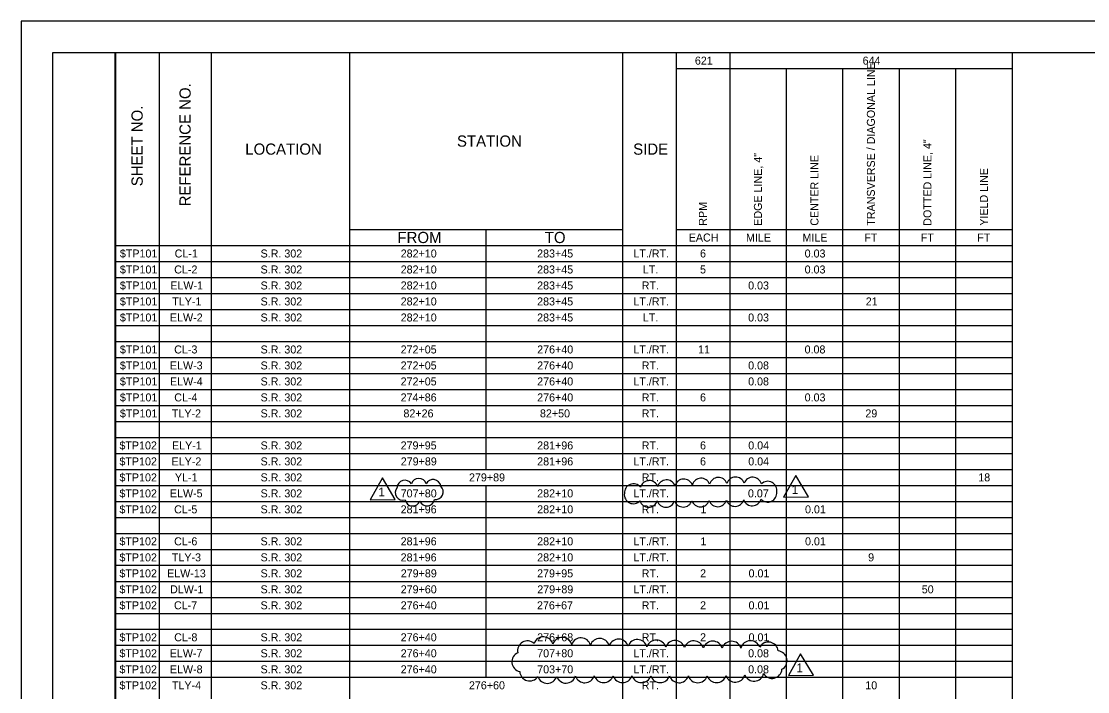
# Model space of a CAD drawing. Extents: x 0 to 34, y 0 to 22.
# Drawn here: x 0 to 17, y 11.3 to 22 of the extents above; entities that cross this region are included whole.
import ezdxf

# ---------------------------------------------------------------- set-up
doc = ezdxf.new("R2010")
doc.units = 0
for name, color, linetype in [('SC_Scratch2', 7, 'Continuous'), ('SH_Border', 7, 'Continuous'), ('SH_Cut_Line', 7, 'Continuous'), ('SH_Data', 7, 'Continuous'), ('SH_Text', 7, 'Continuous')]:
    doc.layers.add(name, color=color, linetype=linetype)

msp = doc.modelspace()

# ---------------------------------------------------------------- linework, layer by layer
at = {"layer": 'SC_Scratch2'}
for points in [[(5.962, 14.373), (5.757, 14.716), (5.563, 14.368)], [(12.55, 14.413), (12.346, 14.755), (12.152, 14.407)], [(12.627, 11.567), (12.422, 11.909), (12.228, 11.561)]]:
    msp.add_lwpolyline(points, close=True, dxfattribs=at)
for centre, radius, start, end in [((6.113, 14.555), 0.124, 32.3184, 177.3184), ((6.336, 14.584), 0.124, 17.5, 162.5), ((6.564, 14.566), 0.124, 8.4917, 153.4917), ((9.758, 14.477), 0.144, 38.7518, 183.7518), ((10.01, 14.529), 0.144, 19.5813, 164.5813), ((10.286, 14.541), 0.144, 20.0695, 165.0695), ((10.562, 14.554), 0.144, 20.3092, 165.3092), ((10.837, 14.567), 0.144, 20.3857, 165.3857), ((11.112, 14.579), 0.144, 19.6335, 164.6335), ((11.386, 14.586), 0.144, 18.1718, 163.1718), ((11.659, 14.582), 0.144, 15.1046, 160.1046), ((11.901, 14.517), 0.144, 349.9389, 134.9389), ((6.085, 14.483), 0.124, 140.5725, 285.5725), ((6.603, 14.493), 0.123, 262.705, 47.705), ((9.757, 14.448), 0.144, 172.0953, 317.0953), ((11.899, 14.474), 0.145, 222.0236, 7.0236), ((6.239, 14.391), 0.124, 192.5799, 337.5799), ((6.466, 14.394), 0.124, 204.1379, 349.1379), ((10.001, 14.392), 0.144, 197.1764, 342.1764), ((10.276, 14.392), 0.144, 197.8033, 342.8033), ((10.552, 14.394), 0.144, 197.9714, 342.9714), ((10.827, 14.397), 0.144, 198.0611, 343.0611), ((11.103, 14.4), 0.144, 198.2873, 343.2873), ((11.378, 14.405), 0.144, 198.8892, 343.8892), ((11.652, 14.415), 0.145, 200.123, 345.123), ((8.068, 11.959), 0.157, 47.3954, 192.3954), ((8.323, 12.023), 0.157, 15.8432, 160.8432), ((8.623, 12.014), 0.157, 15.8432, 160.8432), ((8.922, 12.006), 0.157, 15.8432, 160.8432), ((9.222, 11.997), 0.157, 15.8432, 160.8432), ((9.522, 11.988), 0.157, 15.8432, 160.8432), ((9.822, 11.98), 0.157, 15.8994, 160.8994), ((10.122, 11.972), 0.157, 16.0369, 161.0369), ((10.422, 11.965), 0.157, 16.2188, 161.2188), ((10.722, 11.959), 0.157, 16.4757, 161.4757), ((11.023, 11.954), 0.157, 16.8801, 161.8801), ((11.323, 11.953), 0.157, 17.6722, 162.6722), ((11.625, 11.961), 0.157, 20.3498, 165.3498), ((11.91, 11.94), 0.157, 5.9617, 150.9617), ((7.977, 11.781), 0.157, 113.5219, 258.5219), ((12.05, 11.8), 0.157, 298.8755, 83.8755), ((8.103, 11.633), 0.157, 182.0686, 327.0686), ((9.585, 11.607), 0.157, 197.5241, 342.5241), ((9.885, 11.607), 0.157, 197.3438, 342.3438), ((11.084, 11.606), 0.157, 198.3726, 343.3726), ((11.383, 11.614), 0.157, 199.5171, 344.5171), ((11.68, 11.63), 0.157, 201.7062, 346.7062), ((11.969, 11.674), 0.157, 210.6115, 355.6115), ((8.385, 11.595), 0.157, 197.644, 342.644), ((8.683, 11.599), 0.157, 198.8809, 343.8809), ((8.984, 11.604), 0.157, 198.162, 343.162), ((9.284, 11.607), 0.157, 197.7754, 342.7754), ((10.185, 11.606), 0.157, 197.2063, 342.2063), ((10.485, 11.604), 0.157, 197.1755, 342.1755), ((10.784, 11.604), 0.157, 197.6389, 342.6389)]:
    msp.add_arc(centre, radius, start, end, dxfattribs=at)
at = {"layer": 'SH_Border'}
for points in [[(0.5, 21.5), (1.5, 21.5), (1.5, 0.5), (0.5, 0.5)], [(1.5, 21.5), (33.5, 21.5), (33.5, 0.5), (1.5, 0.5)]]:
    msp.add_lwpolyline(points, close=True, dxfattribs=at)
at = {"layer": 'SH_Cut_Line'}
msp.add_lwpolyline([(0, 0), (34, 0), (34, 22), (0, 22)], close=True, dxfattribs=at)
at = {"layer": 'SH_Data'}
for p, q in [((1.493, 21.5), (15.796, 21.5)), ((1.493, 21.5), (1.493, 1.569)), ((2.198, 21.5), (2.198, 2.095)), ((3.024, 21.5), (3.024, 2.095)), ((5.23, 21.5), (5.23, 2.095)), ((9.582, 21.5), (9.582, 2.095)), ((10.438, 21.5), (10.438, 1.569)), ((11.293, 21.5), (11.293, 1.569)), ((15.796, 21.5), (15.796, 1.569)), ((10.438, 21.245), (15.796, 21.245)), ((12.194, 21.245), (12.194, 1.569)), ((13.094, 21.245), (13.094, 1.569)), ((13.995, 21.245), (13.995, 1.569)), ((14.895, 21.245), (14.895, 1.569)), ((5.23, 18.678), (9.582, 18.678)), ((7.406, 18.678), (7.406, 14.851)), ((10.438, 18.678), (15.796, 18.678)), ((1.493, 18.423), (15.796, 18.423)), ((1.493, 18.168), (15.796, 18.168)), ((1.493, 17.913), (15.796, 17.913)), ((1.493, 17.658), (15.796, 17.658)), ((1.493, 17.403), (15.796, 17.403)), ((1.493, 17.148), (15.796, 17.148)), ((1.493, 16.893), (15.796, 16.893)), ((1.493, 16.637), (15.796, 16.637)), ((1.493, 16.382), (15.796, 16.382)), ((1.493, 16.127), (15.796, 16.127)), ((1.493, 15.872), (15.796, 15.872)), ((1.493, 15.617), (15.796, 15.617)), ((1.493, 15.362), (15.796, 15.362)), ((1.493, 15.107), (15.796, 15.107)), ((1.493, 14.851), (15.796, 14.851)), ((1.493, 14.596), (15.796, 14.596)), ((7.406, 14.596), (7.406, 11.535)), ((1.493, 14.341), (15.796, 14.341)), ((1.493, 14.086), (15.796, 14.086)), ((1.493, 13.831), (15.796, 13.831)), ((1.493, 13.576), (15.796, 13.576)), ((1.493, 13.321), (15.796, 13.321)), ((1.493, 13.065), (15.796, 13.065)), ((1.493, 12.81), (15.796, 12.81)), ((1.493, 12.555), (15.796, 12.555)), ((1.493, 12.3), (15.796, 12.3)), ((1.493, 12.045), (15.796, 12.045)), ((1.493, 11.79), (15.796, 11.79)), ((1.493, 11.535), (15.796, 11.535))]:
    msp.add_line(p, q, dxfattribs=at)

# ---------------------------------------------------------------- texts
at = {"layer": 'SC_Scratch2'}
for p in [(5.692, 14.421), (12.281, 14.461), (12.357, 11.615)]:
    msp.add_text('1', height=0.14, dxfattribs=at).set_placement(p)
at = {"layer": 'SH_Text'}
for s, height, p in [('621', 0.1276, (10.738, 21.309)), ('644', 0.1276, (13.412, 21.309)), ('STATION', 0.1786, (6.945, 20)), ('LOCATION', 0.1786, (3.57, 19.872)), ('SIDE', 0.1786, (9.754, 19.872)), ('FROM', 0.1786, (5.996, 18.462)), ('TO', 0.1786, (8.345, 18.462)), ('EACH', 0.1276, (10.64, 18.487)), ('MILE', 0.1276, (11.553, 18.487)), ('MILE', 0.1276, (12.453, 18.487)), ('FT', 0.1276, (13.439, 18.487)), ('FT', 0.1276, (14.339, 18.487)), ('FT', 0.1276, (15.24, 18.487)), ('$TP101', 0.1276, (1.571, 18.232)), ('CL-1', 0.1276, (2.444, 18.232)), ('S.R. 302', 0.1276, (3.814, 18.232)), ('282+10', 0.1276, (6.048, 18.232)), ('283+45', 0.1276, (8.223, 18.232)), ('LT./RT.', 0.1276, (9.758, 18.232)), ('6', 0.128, (10.82, 18.232)), ('0.03', 0.1276, (12.488, 18.232)), ('$TP101', 0.1276, (1.571, 17.977)), ('CL-2', 0.1276, (2.437, 17.977)), ('S.R. 302', 0.1276, (3.814, 17.977)), ('282+10', 0.1276, (6.048, 17.977)), ('283+45', 0.1276, (8.223, 17.977)), ('LT.', 0.1276, (9.908, 17.977)), ('5', 0.128, (10.82, 17.977)), ('0.03', 0.1276, (12.488, 17.977)), ('$TP101', 0.1276, (1.571, 17.722)), ('S.R. 302', 0.1276, (3.814, 17.722)), ('282+10', 0.1276, (6.048, 17.722)), ('283+45', 0.1276, (8.223, 17.722)), ('0.03', 0.1276, (11.587, 17.722)), ('ELW-1', 0.1276, (2.375, 17.722)), ('RT.', 0.1276, (9.89, 17.722)), ('$TP101', 0.1276, (1.571, 17.467)), ('TLY-1', 0.1276, (2.406, 17.467)), ('S.R. 302', 0.1276, (3.814, 17.467)), ('282+10', 0.1276, (6.048, 17.467)), ('283+45', 0.1276, (8.223, 17.467)), ('LT./RT.', 0.1276, (9.758, 17.467)), ('21', 0.1276, (13.462, 17.467)), ('$TP101', 0.1276, (1.571, 17.211)), ('ELW-2', 0.1276, (2.369, 17.211)), ('S.R. 302', 0.1276, (3.814, 17.211)), ('282+10', 0.1276, (6.048, 17.211)), ('283+45', 0.1276, (8.223, 17.211)), ('0.03', 0.1276, (11.587, 17.211)), ('LT.', 0.1276, (9.908, 17.211)), ('$TP101', 0.1276, (1.571, 16.701)), ('CL-3', 0.1276, (2.437, 16.701)), ('S.R. 302', 0.1276, (3.814, 16.701)), ('272+05', 0.1276, (6.047, 16.701)), ('276+40', 0.1276, (8.224, 16.701)), ('LT./RT.', 0.1276, (9.758, 16.701)), ('0.08', 0.1276, (12.487, 16.701)), ('11', 0.1276, (10.789, 16.701)), ('$TP101', 0.1276, (1.571, 16.446)), ('ELW-3', 0.1276, (2.369, 16.446)), ('S.R. 302', 0.1276, (3.814, 16.446)), ('272+05', 0.1276, (6.047, 16.446)), ('276+40', 0.1276, (8.224, 16.446)), ('RT.', 0.1276, (9.89, 16.446)), ('0.08', 0.1276, (11.587, 16.446)), ('$TP101', 0.1276, (1.571, 16.191)), ('S.R. 302', 0.1276, (3.814, 16.191)), ('272+05', 0.1276, (6.047, 16.191)), ('276+40', 0.1276, (8.224, 16.191)), ('LT./RT.', 0.1276, (9.758, 16.191)), ('0.08', 0.1276, (11.587, 16.191)), ('ELW-4', 0.1276, (2.37, 16.191)), ('$TP101', 0.1276, (1.571, 15.936)), ('CL-4', 0.1276, (2.438, 15.936)), ('S.R. 302', 0.1276, (3.814, 15.936)), ('274+86', 0.1276, (6.047, 15.936)), ('276+40', 0.1276, (8.224, 15.936)), ('RT.', 0.1276, (9.89, 15.936)), ('6', 0.128, (10.82, 15.936)), ('0.03', 0.1276, (12.488, 15.936)), ('$TP101', 0.1276, (1.571, 15.681)), ('TLY-2', 0.1276, (2.4, 15.681)), ('S.R. 302', 0.1276, (3.814, 15.681)), ('82+26', 0.1276, (6.092, 15.681)), ('82+50', 0.1276, (8.268, 15.681)), ('29', 0.1276, (13.456, 15.681)), ('RT.', 0.1276, (9.89, 15.681)), ('$TP102', 0.1276, (1.564, 15.17)), ('ELY-1', 0.1276, (2.402, 15.17)), ('S.R. 302', 0.1276, (3.814, 15.17)), ('279+95', 0.1276, (6.047, 15.17)), ('281+96', 0.1276, (8.224, 15.17)), ('RT.', 0.1276, (9.89, 15.17)), ('6', 0.128, (10.82, 15.17)), ('0.04', 0.1276, (11.589, 15.17)), ('$TP102', 0.1276, (1.564, 14.915)), ('ELY-2', 0.1276, (2.395, 14.915)), ('S.R. 302', 0.1276, (3.814, 14.915)), ('279+89', 0.1276, (6.049, 14.915)), ('281+96', 0.1276, (8.224, 14.915)), ('LT./RT.', 0.1276, (9.758, 14.915)), ('6', 0.128, (10.82, 14.915)), ('0.04', 0.1276, (11.589, 14.915)), ('$TP102', 0.1276, (1.564, 14.66)), ('YL-1', 0.1276, (2.448, 14.66)), ('S.R. 302', 0.1276, (3.814, 14.66)), ('279+89', 0.1276, (7.137, 14.66)), ('RT.', 0.1276, (9.89, 14.66)), ('18', 0.1276, (15.256, 14.66)), ('$TP102', 0.1276, (1.564, 14.405)), ('ELW-5', 0.1276, (2.368, 14.405)), ('S.R. 302', 0.1276, (3.814, 14.405)), ('707+80', 0.1276, (6.048, 14.405)), ('282+10', 0.1276, (8.224, 14.405)), ('LT./RT.', 0.1276, (9.758, 14.405)), ('0.07', 0.1276, (11.584, 14.405)), ('$TP102', 0.1276, (1.564, 14.15)), ('CL-5', 0.1276, (2.436, 14.15)), ('S.R. 302', 0.1276, (3.814, 14.15)), ('281+96', 0.1276, (6.047, 14.15)), ('282+10', 0.1276, (8.224, 14.15)), ('RT.', 0.1276, (9.89, 14.15)), ('1', 0.128, (10.827, 14.15)), ('0.01', 0.1276, (12.494, 14.15)), ('$TP102', 0.1276, (1.564, 13.64)), ('LT./RT.', 0.1276, (9.758, 13.64)), ('CL-6', 0.1276, (2.436, 13.64)), ('S.R. 302', 0.1276, (3.814, 13.64)), ('281+96', 0.1276, (6.047, 13.64)), ('282+10', 0.1276, (8.224, 13.64)), ('1', 0.128, (10.827, 13.64)), ('0.01', 0.1276, (12.494, 13.64)), ('$TP102', 0.1276, (1.564, 13.384)), ('TLY-3', 0.1276, (2.4, 13.384)), ('S.R. 302', 0.1276, (3.814, 13.384)), ('281+96', 0.1276, (6.047, 13.384)), ('282+10', 0.1276, (8.224, 13.384)), ('LT./RT.', 0.1276, (9.758, 13.384)), ('9', 0.128, (13.5, 13.384)), ('$TP102', 0.1276, (1.564, 13.129)), ('ELW-13', 0.1276, (2.324, 13.129)), ('S.R. 302', 0.1276, (3.814, 13.129)), ('279+89', 0.1276, (6.049, 13.129)), ('279+95', 0.1276, (8.223, 13.129)), ('RT.', 0.1276, (9.89, 13.129)), ('2', 0.128, (10.821, 13.129)), ('0.01', 0.1276, (11.594, 13.129)), ('$TP102', 0.1276, (1.564, 12.874)), ('DLW-1', 0.1276, (2.371, 12.874)), ('S.R. 302', 0.1276, (3.814, 12.874)), ('279+60', 0.1276, (6.048, 12.874)), ('279+89', 0.1276, (8.225, 12.874)), ('LT./RT.', 0.1276, (9.758, 12.874)), ('50', 0.1276, (14.355, 12.874)), ('$TP102', 0.1276, (1.564, 12.619)), ('CL-7', 0.1276, (2.434, 12.619)), ('S.R. 302', 0.1276, (3.814, 12.619)), ('276+40', 0.1276, (6.048, 12.619)), ('276+67', 0.1276, (8.221, 12.619)), ('RT.', 0.1276, (9.89, 12.619)), ('2', 0.128, (10.821, 12.619)), ('0.01', 0.1276, (11.594, 12.619)), ('$TP102', 0.1276, (1.564, 12.109)), ('CL-8', 0.1276, (2.437, 12.109)), ('S.R. 302', 0.1276, (3.814, 12.109)), ('276+40', 0.1276, (6.048, 12.109)), ('276+68', 0.1276, (8.224, 12.109)), ('RT.', 0.1276, (9.89, 12.109)), ('2', 0.128, (10.821, 12.109)), ('0.01', 0.1276, (11.594, 12.109)), ('$TP102', 0.1276, (1.564, 11.854)), ('ELW-7', 0.1276, (2.366, 11.854)), ('S.R. 302', 0.1276, (3.814, 11.854)), ('276+40', 0.1276, (6.048, 11.854)), ('707+80', 0.1276, (8.224, 11.854)), ('LT./RT.', 0.1276, (9.758, 11.854)), ('0.08', 0.1276, (11.587, 11.854)), ('$TP102', 0.1276, (1.564, 11.598)), ('LT./RT.', 0.1276, (9.758, 11.598)), ('ELW-8', 0.1276, (2.368, 11.598)), ('S.R. 302', 0.1276, (3.814, 11.598)), ('276+40', 0.1276, (6.048, 11.598)), ('703+70', 0.1276, (8.224, 11.598)), ('0.08', 0.1276, (11.587, 11.598)), ('$TP102', 0.1276, (1.564, 11.343)), ('TLY-4', 0.1276, (2.401, 11.343)), ('S.R. 302', 0.1276, (3.814, 11.343)), ('276+60', 0.1276, (7.136, 11.343)), ('RT.', 0.1276, (9.89, 11.343)), ('10', 0.1276, (13.455, 11.343))]:
    msp.add_text(s, height=height, dxfattribs=at).set_placement(p)
for s, height, p in [('TRANSVERSE / DIAGONAL LINE', 0.12757, (13.608, 18.739)), ('REFERENCE NO.', 0.1786, (2.7, 19.048)), ('SHEET NO.', 0.1786, (1.935, 19.368)), ('DOTTED LINE, 4"', 0.12757, (14.509, 18.739)), ('EDGE LINE, 4"', 0.12757, (11.807, 18.739)), ('CENTER LINE', 0.12757, (12.708, 18.739)), ('YIELD LINE', 0.1276, (15.409, 18.739)), ('RPM', 0.1276, (10.929, 18.739))]:
    msp.add_text(s, height=height, rotation=90, dxfattribs=at).set_placement(p)

doc.saveas('drawing.dxf')
